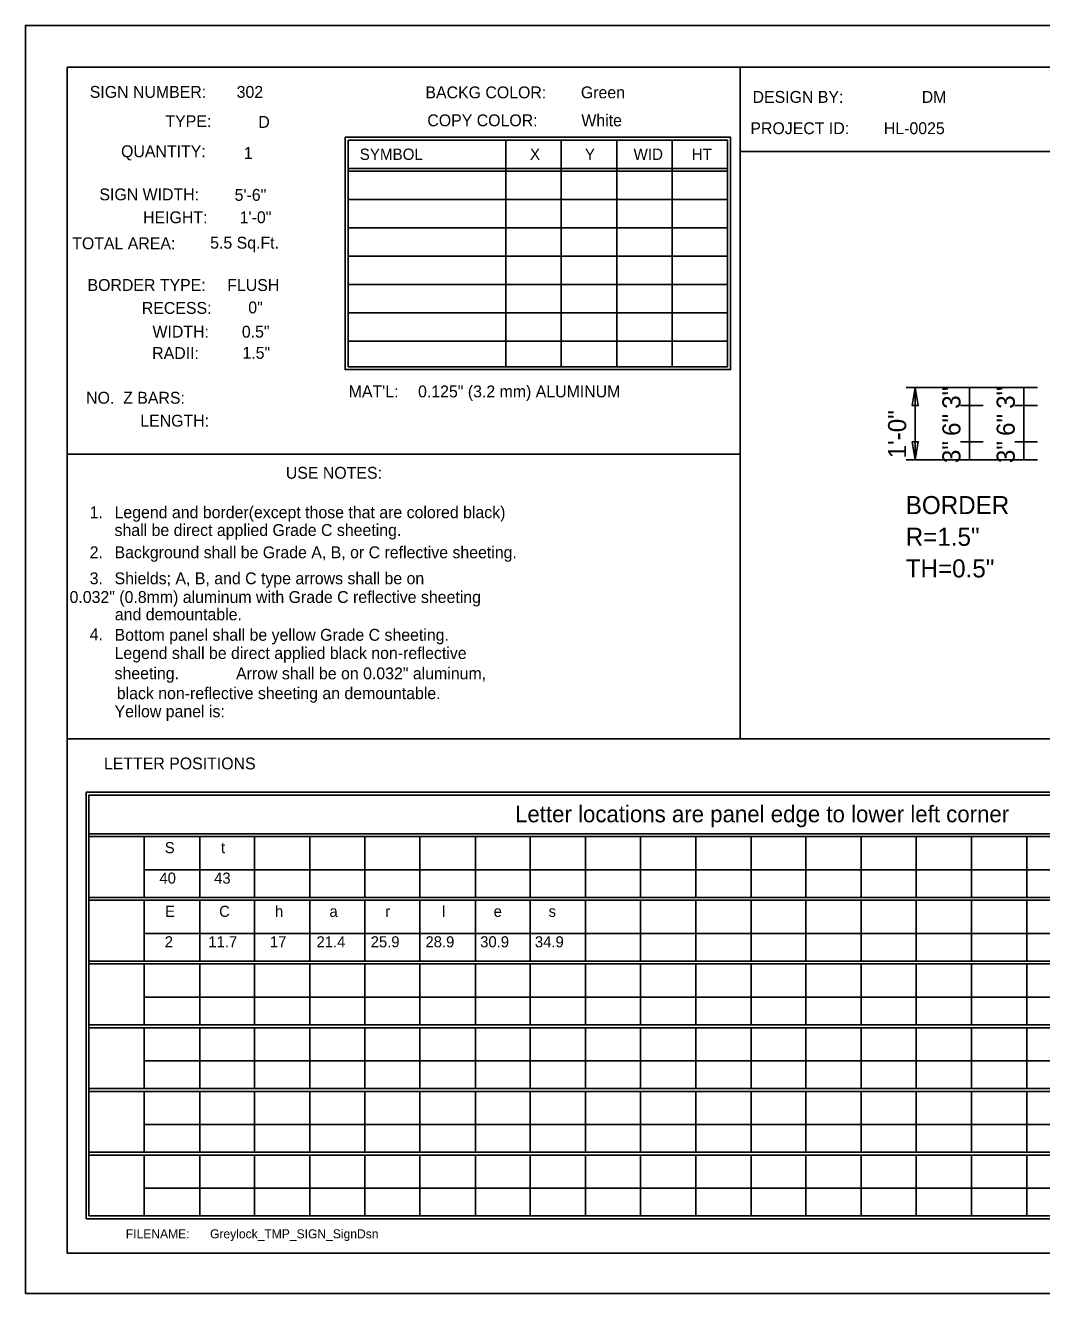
# Model space of a CAD drawing. Extents: x 1708.4 to 1771.6, y 238.3 to 283.4.
# Drawn here: x 1741.56 to 1758.4, y 262.41 to 283.44 of the extents above; entities that cross this region are included whole.
import ezdxf

# ---------------------------------------------------------------- set-up
doc = ezdxf.new("R2010")
doc.units = 0
for name, color, linetype in [('Level 10', 7, 'Continuous'), ('Level 5', 7, 'Continuous'), ('Level 6', 7, 'Continuous'), ('Level 7', 7, 'Continuous'), ('Level 8', 7, 'Continuous'), ('Level 9', 7, 'Continuous')]:
    doc.layers.add(name, color=color, linetype=linetype)

msp = doc.modelspace()

# ---------------------------------------------------------------- linework, layer by layer
at = {"layer": 'Level 5'}
for p, q in [((1756.533, 277.433), (1756.158, 277.433)), ((1756.308, 276.233), (1756.308, 277.433)), ((1758.333, 277.433), (1756.533, 277.433)), ((1757.433, 277.433), (1757.058, 277.433)), ((1757.208, 277.133), (1757.208, 277.433)), ((1758.333, 277.433), (1757.958, 277.433)), ((1758.108, 277.133), (1758.108, 277.433)), ((1757.433, 277.133), (1757.058, 277.133)), ((1757.433, 277.133), (1757.058, 277.133)), ((1757.208, 277.133), (1757.208, 276.533)), ((1758.333, 277.133), (1757.958, 277.133)), ((1758.333, 277.133), (1757.958, 277.133)), ((1758.108, 277.133), (1758.108, 276.533)), ((1757.433, 276.533), (1757.058, 276.533)), ((1757.433, 276.533), (1757.058, 276.533)), ((1757.208, 276.233), (1757.208, 276.533)), ((1758.333, 276.533), (1757.958, 276.533)), ((1758.333, 276.533), (1757.958, 276.533)), ((1758.108, 276.233), (1758.108, 276.533)), ((1756.533, 276.233), (1756.158, 276.233)), ((1758.333, 276.233), (1756.533, 276.233)), ((1757.433, 276.233), (1757.058, 276.233)), ((1758.333, 276.233), (1757.958, 276.233))]:
    msp.add_line(p, q, dxfattribs=at)
for points in [[(1756.308, 277.433), (1756.358, 277.133), (1756.258, 277.133)], [(1756.308, 276.233), (1756.358, 276.533), (1756.258, 276.533)]]:
    msp.add_lwpolyline(points, close=True, dxfattribs=at)
at = {"layer": 'Level 6'}
for p, q in [((1753.405, 282.741), (1753.405, 271.606)), ((1749.52, 281.533), (1749.52, 277.776)), ((1750.44, 281.533), (1750.44, 277.776)), ((1751.36, 281.533), (1751.36, 277.776)), ((1752.28, 281.533), (1752.28, 277.776)), ((1753.405, 281.344), (1770.56, 281.344)), ((1746.906, 281.063), (1753.199, 281.063)), ((1746.906, 281.017), (1753.199, 281.017)), ((1746.906, 280.547), (1753.199, 280.547)), ((1746.906, 280.078), (1753.199, 280.078)), ((1746.906, 279.608), (1753.199, 279.608)), ((1746.906, 279.139), (1753.199, 279.139)), ((1746.906, 278.669), (1753.199, 278.669)), ((1746.906, 278.199), (1753.199, 278.199)), ((1753.405, 276.327), (1742.248, 276.327)), ((1742.248, 271.606), (1753.405, 271.606)), ((1753.405, 271.606), (1770.56, 271.606)), ((1742.611, 270.034), (1764.378, 270.034)), ((1742.611, 269.988), (1764.378, 269.988)), ((1743.529, 269.988), (1743.529, 268.978)), ((1744.447, 269.988), (1744.447, 268.978)), ((1745.355, 269.988), (1745.355, 268.978)), ((1746.273, 269.988), (1746.273, 268.978)), ((1747.182, 269.988), (1747.182, 268.978)), ((1748.099, 269.988), (1748.099, 268.978)), ((1749.017, 269.988), (1749.017, 268.978)), ((1749.926, 269.988), (1749.926, 268.978)), ((1750.843, 269.988), (1750.843, 268.978)), ((1751.752, 269.988), (1751.752, 268.978)), ((1752.67, 269.988), (1752.67, 268.978)), ((1753.587, 269.988), (1753.587, 268.978)), ((1754.496, 269.988), (1754.496, 268.978)), ((1755.414, 269.988), (1755.414, 268.978)), ((1756.322, 269.988), (1756.322, 268.978)), ((1757.24, 269.988), (1757.24, 268.978)), ((1758.158, 269.988), (1758.158, 268.978)), ((1743.529, 269.437), (1764.378, 269.437)), ((1742.611, 268.978), (1764.378, 268.978)), ((1742.611, 268.932), (1764.378, 268.932)), ((1743.529, 268.932), (1743.529, 267.922)), ((1744.447, 268.932), (1744.447, 267.922)), ((1745.355, 268.932), (1745.355, 267.922)), ((1746.273, 268.932), (1746.273, 267.922)), ((1747.182, 268.932), (1747.182, 267.922)), ((1748.099, 268.932), (1748.099, 267.922)), ((1749.017, 268.932), (1749.017, 267.922)), ((1749.926, 268.932), (1749.926, 267.922)), ((1750.843, 268.932), (1750.843, 267.922)), ((1751.752, 268.932), (1751.752, 267.922)), ((1752.67, 268.932), (1752.67, 267.922)), ((1753.587, 268.932), (1753.587, 267.922)), ((1754.496, 268.932), (1754.496, 267.922)), ((1755.414, 268.932), (1755.414, 267.922)), ((1756.322, 268.932), (1756.322, 267.922)), ((1757.24, 268.932), (1757.24, 267.922)), ((1758.158, 268.932), (1758.158, 267.922)), ((1743.529, 268.381), (1764.378, 268.381)), ((1742.611, 267.922), (1764.378, 267.922)), ((1742.611, 267.876), (1764.378, 267.876)), ((1743.529, 267.876), (1743.529, 266.866)), ((1744.447, 267.876), (1744.447, 266.866)), ((1745.355, 267.876), (1745.355, 266.866)), ((1746.273, 267.876), (1746.273, 266.866)), ((1747.182, 267.876), (1747.182, 266.866)), ((1748.099, 267.876), (1748.099, 266.866)), ((1749.017, 267.876), (1749.017, 266.866)), ((1749.926, 267.876), (1749.926, 266.866)), ((1750.843, 267.876), (1750.843, 266.866)), ((1751.752, 267.876), (1751.752, 266.866)), ((1752.67, 267.876), (1752.67, 266.866)), ((1753.587, 267.876), (1753.587, 266.866)), ((1754.496, 267.876), (1754.496, 266.866)), ((1755.414, 267.876), (1755.414, 266.866)), ((1756.322, 267.876), (1756.322, 266.866)), ((1757.24, 267.876), (1757.24, 266.866)), ((1758.158, 267.876), (1758.158, 266.866)), ((1743.529, 267.325), (1764.378, 267.325)), ((1742.611, 266.866), (1764.378, 266.866)), ((1742.611, 266.82), (1764.378, 266.82)), ((1743.529, 266.82), (1743.529, 265.81)), ((1744.447, 266.82), (1744.447, 265.81)), ((1745.355, 266.82), (1745.355, 265.81)), ((1746.273, 266.82), (1746.273, 265.81)), ((1747.182, 266.82), (1747.182, 265.81)), ((1748.099, 266.82), (1748.099, 265.81)), ((1749.017, 266.82), (1749.017, 265.81)), ((1749.926, 266.82), (1749.926, 265.81)), ((1750.843, 266.82), (1750.843, 265.81)), ((1751.752, 266.82), (1751.752, 265.81)), ((1752.67, 266.82), (1752.67, 265.81)), ((1753.587, 266.82), (1753.587, 265.81)), ((1754.496, 266.82), (1754.496, 265.81)), ((1755.414, 266.82), (1755.414, 265.81)), ((1756.322, 266.82), (1756.322, 265.81)), ((1757.24, 266.82), (1757.24, 265.81)), ((1758.158, 266.82), (1758.158, 265.81)), ((1743.529, 266.269), (1764.378, 266.269)), ((1742.611, 265.81), (1764.378, 265.81)), ((1742.611, 265.81), (1764.378, 265.81)), ((1742.611, 265.764), (1764.378, 265.764)), ((1742.611, 265.764), (1764.378, 265.764)), ((1743.529, 265.928), (1743.529, 265.81)), ((1743.529, 265.764), (1743.529, 264.821)), ((1743.529, 265.764), (1743.529, 264.754)), ((1744.447, 265.928), (1744.447, 265.81)), ((1744.447, 265.764), (1744.447, 264.821)), ((1744.447, 265.764), (1744.447, 264.754)), ((1745.355, 265.928), (1745.355, 265.81)), ((1745.355, 265.764), (1745.355, 264.821)), ((1745.355, 265.764), (1745.355, 264.754)), ((1746.273, 265.928), (1746.273, 265.81)), ((1746.273, 265.764), (1746.273, 264.821)), ((1746.273, 265.764), (1746.273, 264.754)), ((1747.182, 265.928), (1747.182, 265.81)), ((1747.182, 265.764), (1747.182, 264.821)), ((1747.182, 265.764), (1747.182, 264.754)), ((1748.099, 265.928), (1748.099, 265.81)), ((1748.099, 265.764), (1748.099, 264.821)), ((1748.099, 265.764), (1748.099, 264.754)), ((1749.017, 265.928), (1749.017, 265.81)), ((1749.017, 265.764), (1749.017, 264.821)), ((1749.017, 265.764), (1749.017, 264.754)), ((1749.926, 265.928), (1749.926, 265.81)), ((1749.926, 265.764), (1749.926, 264.821)), ((1749.926, 265.764), (1749.926, 264.754)), ((1750.843, 265.928), (1750.843, 265.81)), ((1750.843, 265.764), (1750.843, 264.821)), ((1750.843, 265.764), (1750.843, 264.754)), ((1751.752, 265.928), (1751.752, 265.81)), ((1751.752, 265.764), (1751.752, 264.821)), ((1751.752, 265.764), (1751.752, 264.754)), ((1752.67, 265.928), (1752.67, 265.81)), ((1752.67, 265.764), (1752.67, 264.821)), ((1752.67, 265.764), (1752.67, 264.754)), ((1753.587, 265.928), (1753.587, 265.81)), ((1753.587, 265.764), (1753.587, 264.821)), ((1753.587, 265.764), (1753.587, 264.754)), ((1754.496, 265.928), (1754.496, 265.81)), ((1754.496, 265.764), (1754.496, 264.821)), ((1754.496, 265.764), (1754.496, 264.754)), ((1755.414, 265.928), (1755.414, 265.81)), ((1755.414, 265.764), (1755.414, 264.821)), ((1755.414, 265.764), (1755.414, 264.754)), ((1756.322, 265.928), (1756.322, 265.81)), ((1756.322, 265.764), (1756.322, 264.821)), ((1756.322, 265.764), (1756.322, 264.754)), ((1757.24, 265.928), (1757.24, 265.81)), ((1757.24, 265.764), (1757.24, 264.821)), ((1757.24, 265.764), (1757.24, 264.754)), ((1758.158, 265.928), (1758.158, 265.81)), ((1758.158, 265.764), (1758.158, 264.821)), ((1758.158, 265.764), (1758.158, 264.754)), ((1743.529, 265.214), (1764.378, 265.214)), ((1743.529, 265.214), (1764.378, 265.214)), ((1742.611, 264.754), (1764.378, 264.754)), ((1742.611, 264.754), (1764.378, 264.754)), ((1742.611, 264.709), (1764.378, 264.709)), ((1742.611, 264.709), (1764.378, 264.709)), ((1743.529, 264.872), (1743.529, 264.754)), ((1743.529, 264.709), (1743.529, 263.699)), ((1743.529, 264.709), (1743.529, 263.699)), ((1744.447, 264.872), (1744.447, 264.754)), ((1744.447, 264.709), (1744.447, 263.699)), ((1744.447, 264.709), (1744.447, 263.699)), ((1745.355, 264.872), (1745.355, 264.754)), ((1745.355, 264.709), (1745.355, 263.699)), ((1745.355, 264.709), (1745.355, 263.699)), ((1746.273, 264.872), (1746.273, 264.754)), ((1746.273, 264.709), (1746.273, 263.699)), ((1746.273, 264.709), (1746.273, 263.699)), ((1747.182, 264.872), (1747.182, 264.754)), ((1747.182, 264.709), (1747.182, 263.699)), ((1747.182, 264.709), (1747.182, 263.699)), ((1748.099, 264.872), (1748.099, 264.754)), ((1748.099, 264.709), (1748.099, 263.699)), ((1748.099, 264.709), (1748.099, 263.699)), ((1749.017, 264.872), (1749.017, 264.754)), ((1749.017, 264.709), (1749.017, 263.699)), ((1749.017, 264.709), (1749.017, 263.699)), ((1749.926, 264.872), (1749.926, 264.754)), ((1749.926, 264.709), (1749.926, 263.699)), ((1749.926, 264.709), (1749.926, 263.699)), ((1750.843, 264.872), (1750.843, 264.754)), ((1750.843, 264.709), (1750.843, 263.699)), ((1750.843, 264.709), (1750.843, 263.699)), ((1751.752, 264.872), (1751.752, 264.754)), ((1751.752, 264.709), (1751.752, 263.699)), ((1751.752, 264.709), (1751.752, 263.699)), ((1752.67, 264.872), (1752.67, 264.754)), ((1752.67, 264.709), (1752.67, 263.699)), ((1752.67, 264.709), (1752.67, 263.699)), ((1753.587, 264.872), (1753.587, 264.754)), ((1753.587, 264.709), (1753.587, 263.699)), ((1753.587, 264.709), (1753.587, 263.699)), ((1754.496, 264.872), (1754.496, 264.754)), ((1754.496, 264.709), (1754.496, 263.699)), ((1754.496, 264.709), (1754.496, 263.699)), ((1755.414, 264.872), (1755.414, 264.754)), ((1755.414, 264.709), (1755.414, 263.699)), ((1755.414, 264.709), (1755.414, 263.699)), ((1756.322, 264.872), (1756.322, 264.754)), ((1756.322, 264.709), (1756.322, 263.699)), ((1756.322, 264.709), (1756.322, 263.699)), ((1757.24, 264.872), (1757.24, 264.754)), ((1757.24, 264.709), (1757.24, 263.699)), ((1757.24, 264.709), (1757.24, 263.699)), ((1758.158, 264.872), (1758.158, 264.754)), ((1758.158, 264.709), (1758.158, 263.699)), ((1758.158, 264.709), (1758.158, 263.699)), ((1743.529, 264.158), (1764.378, 264.158)), ((1743.529, 264.158), (1764.378, 264.158)), ((1742.564, 263.653), (1764.378, 263.653)), ((1742.611, 263.699), (1764.378, 263.699)), ((1742.611, 263.699), (1764.378, 263.699)), ((1742.611, 263.653), (1764.378, 263.653))]:
    msp.add_line(p, q, dxfattribs=at)
for points in [[(1742.248, 282.741), (1770.56, 282.741), (1770.56, 263.084), (1742.248, 263.084)], [(1746.858, 281.58), (1753.248, 281.58), (1753.248, 277.73), (1746.858, 277.73)], [(1746.906, 281.533), (1753.199, 281.533), (1753.199, 277.776), (1746.906, 277.776)]]:
    msp.add_lwpolyline(points, close=True, dxfattribs=at)
for points in [[(1742.564, 264.821), (1742.564, 270.723), (1764.378, 270.723)], [(1742.611, 264.821), (1742.611, 270.677), (1764.378, 270.677)], [(1742.564, 263.653), (1742.564, 265.928)], [(1742.611, 263.699), (1742.611, 265.928)]]:
    msp.add_lwpolyline(points, dxfattribs=at)
at = {"layer": 'Level 9'}
msp.add_lwpolyline([(1741.558, 262.411), (1771.62, 262.411), (1771.62, 283.435), (1741.558, 283.435)], close=True, dxfattribs=at)

# ---------------------------------------------------------------- texts
at = {"layer": 'Level 10'}
for s, p in [('and demountable.', (1743.041, 273.574)), ('Arrow shall be on 0.032" aluminum,', (1745.05, 272.595)), ('black non-reflective sheeting an demountable.', (1743.073, 272.266))]:
    msp.add_text(s, height=0.19675, dxfattribs=at).set_placement(p)
at = {"layer": 'Level 5'}
for s, p in [('3"', (1757.058, 277.079)), ('3"', (1757.958, 277.079)), ('1\'-0"', (1756.158, 276.257)), ('6"', (1757.058, 276.629)), ('6"', (1757.958, 276.629)), ('3"', (1757.058, 276.179)), ('3"', (1757.958, 276.179))]:
    msp.add_text(s, height=0.3, rotation=90, dxfattribs=at).set_placement(p)
for s, p in [('BORDER', (1756.151, 275.333)), ('R=1.5"', (1756.151, 274.808)), ('TH=0.5"', (1756.151, 274.283))]:
    msp.add_text(s, height=0.3, dxfattribs=at).set_placement(p)
at = {"layer": 'Level 6'}
for s, height, p in [('SIGN NUMBER:', 0.19675, (1742.625, 282.234)), ('BACKG COLOR:', 0.19675, (1748.189, 282.226)), ('DESIGN BY:', 0.1968, (1753.612, 282.151)), ('TYPE:', 0.1968, (1743.879, 281.749)), ('COPY COLOR:', 0.19675, (1748.221, 281.763)), ('PROJECT ID:', 0.19675, (1753.576, 281.632)), ('QUANTITY:', 0.1968, (1743.144, 281.25)), ('SIGN WIDTH:', 0.19675, (1742.785, 280.535)), ('HEIGHT:', 0.1968, (1743.509, 280.155)), ('TOTAL AREA:', 0.19675, (1742.334, 279.724)), ('BORDER TYPE:', 0.19675, (1742.588, 279.033)), ('RECESS:', 0.1968, (1743.488, 278.653)), ('WIDTH:', 0.1968, (1743.665, 278.259)), ('RADII:', 0.1968, (1743.66, 277.905)), ('NO.  Z BARS:', 0.19675, (1742.565, 277.164)), ("MAT'L:", 0.1968, (1746.918, 277.269)), ('LENGTH:', 0.1968, (1743.462, 276.784)), ('USE NOTES: ', 0.19675, (1745.875, 275.92)), ('1.', 0.1968, (1742.624, 275.266)), ('Legend and border(except those that are colored black)', 0.19675, (1743.036, 275.266)), ('2.', 0.1968, (1742.624, 274.602)), ('3.', 0.1968, (1742.624, 274.171)), ('4.', 0.1968, (1742.624, 273.242)), ('LETTER POSITIONS', 0.19675, (1742.86, 271.102)), ('Letter locations are panel edge to lower left corner', 0.27545, (1749.675, 270.225))]:
    msp.add_text(s, height=height, rotation=360, dxfattribs=at).set_placement(p)
for s, height, p in [('DM', 0.1968, (1756.416, 282.151)), ('HL-0025', 0.1968, (1755.788, 281.632)), ('SYMBOL', 0.1878, (1747.1, 281.205)), ('X', 0.188, (1749.922, 281.205)), ('Y', 0.188, (1750.832, 281.205)), ('WID', 0.1878, (1751.639, 281.205)), ('HT', 0.1878, (1752.604, 281.205)), ('0.125" (3.2 mm) ALUMINUM', 0.19675, (1748.067, 277.269)), ('shall be direct applied Grade C sheeting.', 0.19675, (1743.036, 274.971)), ('Background shall be Grade A, B, or C reflective sheeting.', 0.19675, (1743.036, 274.602)), ('Shields; A, B, and C type arrows shall be on', 0.19675, (1743.036, 274.171)), ('       0.032" (0.8mm) aluminum with Grade C reflective sheeting', 0.19675, (1741.778, 273.861)), ('S', 0.184, (1743.868, 269.713)), ('t', 0.184, (1744.801, 269.713)), ('40', 0.1836, (1743.78, 269.208)), ('43', 0.1836, (1744.687, 269.208)), ('E', 0.184, (1743.872, 268.657)), ('C', 0.184, (1744.77, 268.657)), ('h', 0.184, (1745.695, 268.657)), ('a', 0.184, (1746.598, 268.657)), ('r', 0.184, (1747.523, 268.657)), ('l', 0.184, (1748.465, 268.657)), ('e', 0.184, (1749.32, 268.657)), ('s', 0.184, (1750.231, 268.657)), ('2', 0.184, (1743.868, 268.152)), ('11.7', 0.1836, (1744.591, 268.152)), ('17', 0.1836, (1745.612, 268.152)), ('21.4', 0.1836, (1746.384, 268.152)), ('25.9', 0.1836, (1747.282, 268.152)), ('28.9', 0.1836, (1748.19, 268.152)), ('30.9', 0.1836, (1749.097, 268.152)), ('34.9', 0.1836, (1750.004, 268.152))]:
    msp.add_text(s, height=height, dxfattribs=at).set_placement(p)
at = {"layer": 'Level 7'}
for s, height, p in [('302', 0.1968, (1745.06, 282.234)), ('Green', 0.1968, (1750.766, 282.226)), ('D', 0.197, (1745.419, 281.736)), ('1', 0.197, (1745.179, 281.221)), ('5\'-6"', 0.1968, (1745.027, 280.527)), ('1\'-0"', 0.1968, (1745.111, 280.156)), ('5.5 Sq.Ft.', 0.1968, (1744.621, 279.734)), ('FLUSH', 0.1968, (1744.904, 279.032)), ('0"', 0.1968, (1745.253, 278.661)), ('0.5"', 0.1968, (1745.146, 278.259)), ('1.5"', 0.1968, (1745.156, 277.909))]:
    msp.add_text(s, height=height, rotation=360, dxfattribs=at).set_placement(p)
for s, height, p in [('White', 0.1968, (1750.774, 281.763)), ('Bottom panel shall be yellow Grade C sheeting.', 0.19675, (1743.036, 273.234)), ('Legend shall be direct applied black non-reflective', 0.19675, (1743.036, 272.932)), ('sheeting.', 0.1968, (1743.036, 272.597)), ('Yellow panel is:', 0.19675, (1743.036, 271.966))]:
    msp.add_text(s, height=height, dxfattribs=at).set_placement(p)
at = {"layer": 'Level 8'}
for s, height, p in [('FILENAME:', 0.1497, (1743.223, 263.328)), ('Greylock_TMP_SIGN_SignDsn', 0.14966, (1744.619, 263.328))]:
    msp.add_text(s, height=height, rotation=360, dxfattribs=at).set_placement(p)

doc.saveas('drawing.dxf')
